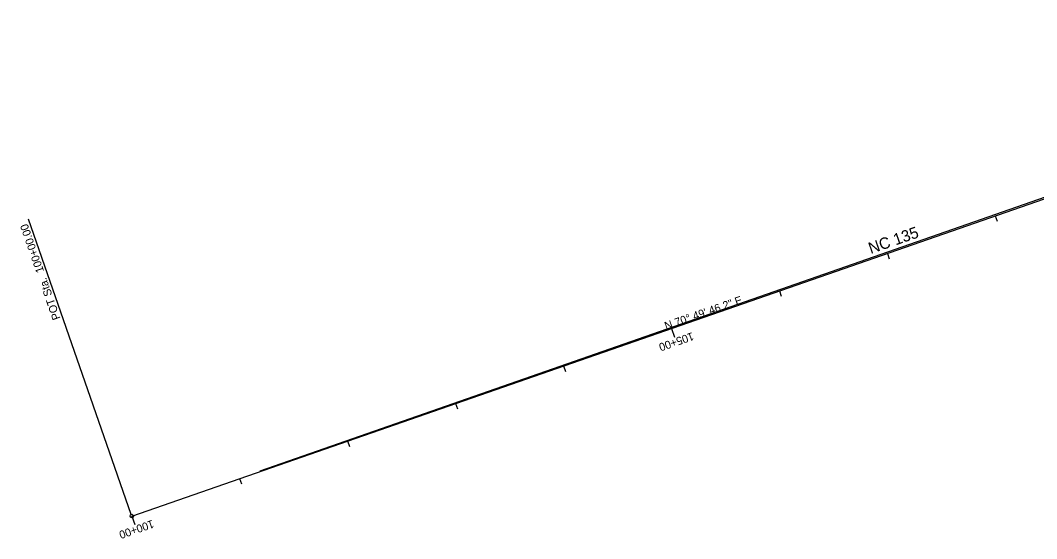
# Model space of a CAD drawing. Extents: x 1722038 to 1726172, y 967033 to 975427.
# Drawn here: x 1722038 to 1722928, y 971143 to 971597 of the extents above; entities that cross this region are included whole.
import ezdxf

# ---------------------------------------------------------------- set-up
doc = ezdxf.new("R2010")
doc.units = 0
for name, color, linetype in [('Prop Horizontal Alignment', 7, 'Continuous'), ('Prop Horizontal Alignment Direction Label', 7, 'Continuous'), ('Prop Horizontal Alignment Station Label', 7, 'Continuous'), ('Prop Horizontal Alignment Tick Label', 7, 'Continuous'), ('Prop Horizontal Alignment Tick Large', 7, 'Continuous'), ('Prop Horizontal Alignment Tick Small', 7, 'Continuous')]:
    doc.layers.add(name, color=color, linetype=linetype)

msp = doc.modelspace()

# ---------------------------------------------------------------- linework, layer by layer
at = {"layer": 'Prop Horizontal Alignment'}
for p, q in [((1722248.35, 971202.25), (1723377.68, 971596.63)), ((1722135.84, 971162.75), (1723341.23, 971581.82))]:
    msp.add_line(p, q, dxfattribs=at)
at = {"layer": 'Prop Horizontal Alignment Station Label'}
msp.add_line((1722135.34, 971164.17), (1722045.53, 971422.5), dxfattribs=at)
msp.add_circle((1722135.84, 971162.75), 1.5, dxfattribs=at)
at = {"layer": 'Prop Horizontal Alignment Tick Large'}
for p, q in [((1722608.11, 971326.94), (1722610.74, 971319.39)), ((1722135.84, 971162.75), (1722138.46, 971155.2))]:
    msp.add_line(p, q, dxfattribs=at)
at = {"layer": 'Prop Horizontal Alignment Tick Small'}
for p, q in [((1722891.47, 971425.46), (1722893.11, 971420.74)), ((1722797.02, 971392.62), (1722798.66, 971387.9)), ((1722702.56, 971359.78), (1722704.2, 971355.06)), ((1722513.65, 971294.11), (1722515.3, 971289.38)), ((1722419.2, 971261.27), (1722420.84, 971256.55)), ((1722324.74, 971228.43), (1722326.39, 971223.71)), ((1722230.29, 971195.59), (1722231.93, 971190.87))]:
    msp.add_line(p, q, dxfattribs=at)

# ---------------------------------------------------------------- texts
at = {"layer": 'Prop Horizontal Alignment Direction Label'}
msp.add_text('N 70%%d 49\' 46.2" E', height=7, rotation=19.1705, dxfattribs=at).set_placement((1722603.48, 971325.55))
at = {"layer": 'Prop Horizontal Alignment Station Label'}
msp.add_text('POT Sta.  100+00.00', height=7, rotation=109.1705, dxfattribs=at).set_placement((1722073.57, 971335.75))
at = {"layer": 'Prop Horizontal Alignment Tick Label'}
for s, height, rotation, p in [('NC 135', 10, 19.1705, (1722782.52, 971392.04)), ('105+00', 7, 199.1705, (1722626.21, 971323.71)), ('100+00', 7, 199.1705, (1722153.84, 971159.48))]:
    msp.add_text(s, height=height, rotation=rotation, dxfattribs=at).set_placement(p)

doc.saveas('drawing.dxf')
